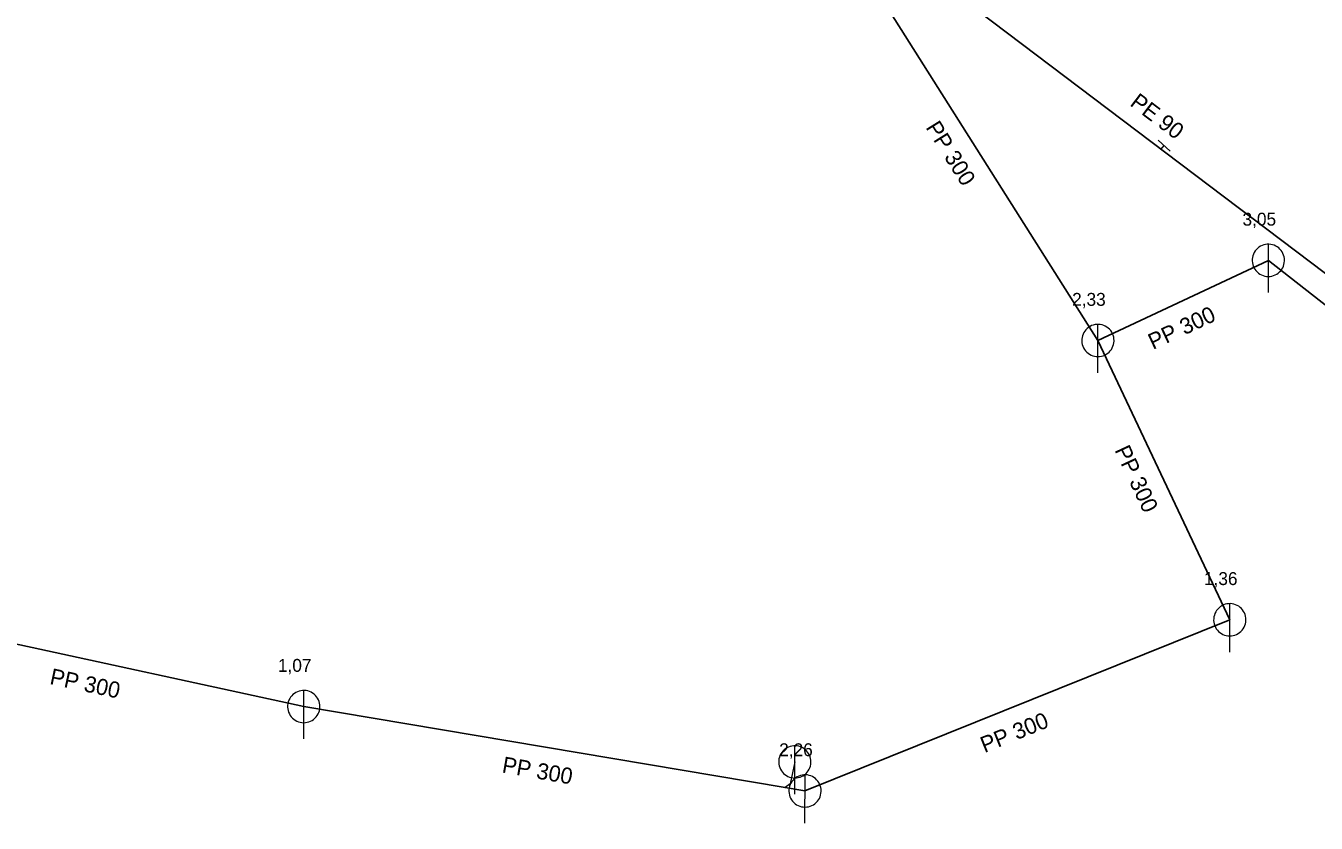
# Model space of a CAD drawing. Extents: x -683466 to -682479, y -996772 to -995963.
# Drawn here: x -683391.7 to -683311.7, y -996081.7 to -996032.3 of the extents above; entities that cross this region are included whole.
import ezdxf

# ---------------------------------------------------------------- set-up
doc = ezdxf.new("R2010")
doc.units = 0
doc.header["$LTSCALE"] = 0.4
doc.layers.add('1', color=7, linetype='Continuous')
for name, color, linetype, lineweight in [('11', 7, 'Continuous', 13), ('14', 7, 'Continuous', 25), ('17', 7, 'Continuous', 25), ('22', 7, 'Continuous', 13), ('34', 7, 'Continuous', 13)]:
    doc.layers.add(name, color=color, linetype=linetype, lineweight=lineweight)

msp = doc.modelspace()

# ---------------------------------------------------------------- linework, layer by layer
at = {"layer": '11'}
msp.add_lwpolyline([(-683344.05, -996077.91), (-683344.339, -996079.274), (-683344.657, -996079.502)], dxfattribs=at)
at = {"layer": '14'}
for p, q in [((-683340.109, -996028.32), (-683325.27, -996051.789)), ((-683374.48, -996074.48), (-683399.35, -996069.07)), ((-683317.1, -996069.1), (-683343.42, -996079.71))]:
    msp.add_line(p, q, dxfattribs=at)
at = {"layer": '14', "lineweight": 13}
msp.add_line((-683321.354, -996039.926), (-683321.16, -996039.71), dxfattribs=at)
at = {"layer": '14'}
for points in [[(-683314.71, -996046.82), (-683325.27, -996051.789), (-683317.1, -996069.1)], [(-683291.78, -996064.829), (-683303.509, -996055.596), (-683305.57, -996053.982), (-683314.71, -996046.82)], [(-683343.42, -996079.71), (-683344.657, -996079.502), (-683374.48, -996074.48)]]:
    msp.add_lwpolyline(points, dxfattribs=at)
at = {"layer": '17'}
msp.add_lwpolyline([(-683345.87, -996001.27), (-683340.96, -996022.3), (-683339.832, -996025.943), (-683304.056, -996053.017), (-683282.79, -996067.766), (-683274.905, -996069.189), (-683269.5, -996070.27), (-683248.91, -996070.167), (-683229.542, -996070.96), (-683219.888, -996069.96)], dxfattribs=at)
at = {"layer": '22'}
for p, q in [((-683314.71, -996048.82), (-683314.709, -996045.82)), ((-683325.27, -996053.789), (-683325.269, -996050.789)), ((-683317.1, -996071.1), (-683317.099, -996068.1)), ((-683374.48, -996076.48), (-683374.479, -996073.48)), ((-683344.05, -996079.91), (-683344.049, -996076.91)), ((-683343.42, -996081.71), (-683343.419, -996078.71))]:
    msp.add_line(p, q, dxfattribs=at)
for points in [[(-683313.71, -996046.82), (-683313.715, -996046.711), (-683313.733, -996046.603), (-683313.763, -996046.497), (-683313.803, -996046.396), (-683313.855, -996046.299), (-683313.917, -996046.209), (-683313.989, -996046.126), (-683314.069, -996046.052), (-683314.157, -996045.986), (-683314.251, -996045.931), (-683314.351, -996045.886), (-683314.456, -996045.853), (-683314.563, -996045.831), (-683314.672, -996045.821), (-683314.782, -996045.823), (-683314.89, -996045.837), (-683314.997, -996045.862), (-683315.1, -996045.899), (-683315.198, -996045.948), (-683315.29, -996046.006), (-683315.376, -996046.075), (-683315.453, -996046.152), (-683315.522, -996046.238), (-683315.581, -996046.33), (-683315.629, -996046.428), (-683315.666, -996046.531), (-683315.692, -996046.638), (-683315.706, -996046.746), (-683315.709, -996046.856), (-683315.699, -996046.965), (-683315.678, -996047.072), (-683315.644, -996047.176), (-683315.6, -996047.276), (-683315.545, -996047.371), (-683315.479, -996047.459), (-683315.405, -996047.539), (-683315.322, -996047.611), (-683315.232, -996047.673), (-683315.136, -996047.725), (-683315.034, -996047.766), (-683314.929, -996047.796), (-683314.821, -996047.814), (-683314.711, -996047.82), (-683314.602, -996047.814), (-683314.494, -996047.796), (-683314.389, -996047.767), (-683314.287, -996047.726), (-683314.19, -996047.674), (-683314.1, -996047.612), (-683314.017, -996047.541), (-683313.942, -996047.461), (-683313.877, -996047.373), (-683313.821, -996047.279), (-683313.777, -996047.179), (-683313.743, -996047.075), (-683313.721, -996046.967), (-683313.711, -996046.858)], [(-683324.27, -996051.789), (-683324.275, -996051.68), (-683324.293, -996051.572), (-683324.323, -996051.466), (-683324.363, -996051.365), (-683324.415, -996051.268), (-683324.477, -996051.178), (-683324.549, -996051.095), (-683324.629, -996051.021), (-683324.717, -996050.955), (-683324.811, -996050.9), (-683324.911, -996050.855), (-683325.016, -996050.822), (-683325.123, -996050.8), (-683325.232, -996050.79), (-683325.342, -996050.792), (-683325.45, -996050.806), (-683325.557, -996050.831), (-683325.66, -996050.868), (-683325.758, -996050.917), (-683325.85, -996050.975), (-683325.936, -996051.044), (-683326.013, -996051.121), (-683326.082, -996051.207), (-683326.141, -996051.299), (-683326.189, -996051.397), (-683326.226, -996051.5), (-683326.252, -996051.607), (-683326.266, -996051.715), (-683326.269, -996051.825), (-683326.259, -996051.934), (-683326.238, -996052.041), (-683326.204, -996052.145), (-683326.16, -996052.245), (-683326.105, -996052.34), (-683326.039, -996052.428), (-683325.965, -996052.508), (-683325.882, -996052.58), (-683325.792, -996052.642), (-683325.696, -996052.694), (-683325.594, -996052.735), (-683325.489, -996052.765), (-683325.381, -996052.783), (-683325.271, -996052.789), (-683325.162, -996052.783), (-683325.054, -996052.765), (-683324.949, -996052.736), (-683324.847, -996052.695), (-683324.75, -996052.643), (-683324.66, -996052.581), (-683324.577, -996052.51), (-683324.502, -996052.43), (-683324.437, -996052.342), (-683324.381, -996052.248), (-683324.337, -996052.148), (-683324.303, -996052.044), (-683324.281, -996051.936), (-683324.271, -996051.827)], [(-683316.1, -996069.1), (-683316.105, -996068.991), (-683316.123, -996068.883), (-683316.153, -996068.777), (-683316.193, -996068.676), (-683316.245, -996068.579), (-683316.307, -996068.489), (-683316.379, -996068.406), (-683316.459, -996068.332), (-683316.547, -996068.266), (-683316.641, -996068.211), (-683316.741, -996068.166), (-683316.846, -996068.133), (-683316.953, -996068.111), (-683317.062, -996068.101), (-683317.172, -996068.103), (-683317.28, -996068.117), (-683317.387, -996068.142), (-683317.49, -996068.179), (-683317.588, -996068.228), (-683317.68, -996068.286), (-683317.766, -996068.355), (-683317.843, -996068.432), (-683317.912, -996068.518), (-683317.971, -996068.61), (-683318.019, -996068.708), (-683318.056, -996068.811), (-683318.082, -996068.918), (-683318.096, -996069.026), (-683318.099, -996069.136), (-683318.089, -996069.245), (-683318.068, -996069.352), (-683318.034, -996069.456), (-683317.99, -996069.556), (-683317.935, -996069.651), (-683317.869, -996069.739), (-683317.795, -996069.819), (-683317.712, -996069.891), (-683317.622, -996069.953), (-683317.526, -996070.005), (-683317.424, -996070.046), (-683317.319, -996070.076), (-683317.211, -996070.094), (-683317.101, -996070.1), (-683316.992, -996070.094), (-683316.884, -996070.076), (-683316.779, -996070.047), (-683316.677, -996070.006), (-683316.58, -996069.954), (-683316.49, -996069.892), (-683316.407, -996069.821), (-683316.332, -996069.741), (-683316.267, -996069.653), (-683316.211, -996069.559), (-683316.167, -996069.459), (-683316.133, -996069.355), (-683316.111, -996069.247), (-683316.101, -996069.138)], [(-683373.48, -996074.48), (-683373.485, -996074.371), (-683373.503, -996074.263), (-683373.533, -996074.157), (-683373.573, -996074.056), (-683373.625, -996073.959), (-683373.687, -996073.869), (-683373.759, -996073.786), (-683373.839, -996073.712), (-683373.927, -996073.646), (-683374.021, -996073.591), (-683374.121, -996073.546), (-683374.226, -996073.513), (-683374.333, -996073.491), (-683374.442, -996073.481), (-683374.552, -996073.483), (-683374.66, -996073.497), (-683374.767, -996073.522), (-683374.87, -996073.559), (-683374.968, -996073.608), (-683375.06, -996073.666), (-683375.146, -996073.735), (-683375.223, -996073.812), (-683375.292, -996073.898), (-683375.351, -996073.99), (-683375.399, -996074.088), (-683375.436, -996074.191), (-683375.462, -996074.298), (-683375.476, -996074.406), (-683375.479, -996074.516), (-683375.469, -996074.625), (-683375.448, -996074.732), (-683375.414, -996074.836), (-683375.37, -996074.936), (-683375.315, -996075.031), (-683375.249, -996075.119), (-683375.175, -996075.199), (-683375.092, -996075.271), (-683375.002, -996075.333), (-683374.906, -996075.385), (-683374.804, -996075.426), (-683374.699, -996075.456), (-683374.591, -996075.474), (-683374.481, -996075.48), (-683374.372, -996075.474), (-683374.264, -996075.456), (-683374.159, -996075.427), (-683374.057, -996075.386), (-683373.96, -996075.334), (-683373.87, -996075.272), (-683373.787, -996075.201), (-683373.712, -996075.121), (-683373.647, -996075.033), (-683373.591, -996074.939), (-683373.547, -996074.839), (-683373.513, -996074.735), (-683373.491, -996074.627), (-683373.481, -996074.518)], [(-683343.05, -996077.91), (-683343.055, -996077.801), (-683343.073, -996077.693), (-683343.103, -996077.587), (-683343.143, -996077.486), (-683343.195, -996077.389), (-683343.257, -996077.299), (-683343.329, -996077.216), (-683343.409, -996077.142), (-683343.497, -996077.076), (-683343.591, -996077.021), (-683343.691, -996076.976), (-683343.796, -996076.943), (-683343.903, -996076.921), (-683344.012, -996076.911), (-683344.122, -996076.913), (-683344.23, -996076.927), (-683344.337, -996076.952), (-683344.44, -996076.989), (-683344.538, -996077.038), (-683344.63, -996077.096), (-683344.716, -996077.165), (-683344.793, -996077.242), (-683344.862, -996077.328), (-683344.921, -996077.42), (-683344.969, -996077.518), (-683345.006, -996077.621), (-683345.032, -996077.728), (-683345.046, -996077.836), (-683345.049, -996077.946), (-683345.039, -996078.055), (-683345.018, -996078.162), (-683344.984, -996078.266), (-683344.94, -996078.366), (-683344.885, -996078.461), (-683344.819, -996078.549), (-683344.745, -996078.629), (-683344.662, -996078.701), (-683344.572, -996078.763), (-683344.476, -996078.815), (-683344.374, -996078.856), (-683344.269, -996078.886), (-683344.161, -996078.904), (-683344.051, -996078.91), (-683343.942, -996078.904), (-683343.834, -996078.886), (-683343.729, -996078.857), (-683343.627, -996078.816), (-683343.53, -996078.764), (-683343.44, -996078.702), (-683343.357, -996078.631), (-683343.282, -996078.551), (-683343.217, -996078.463), (-683343.161, -996078.369), (-683343.117, -996078.269), (-683343.083, -996078.165), (-683343.061, -996078.057), (-683343.051, -996077.948)], [(-683342.42, -996079.71), (-683342.425, -996079.601), (-683342.443, -996079.493), (-683342.473, -996079.387), (-683342.513, -996079.286), (-683342.565, -996079.189), (-683342.627, -996079.099), (-683342.699, -996079.016), (-683342.779, -996078.942), (-683342.867, -996078.876), (-683342.961, -996078.821), (-683343.061, -996078.776), (-683343.166, -996078.743), (-683343.273, -996078.721), (-683343.382, -996078.711), (-683343.492, -996078.713), (-683343.6, -996078.727), (-683343.707, -996078.752), (-683343.81, -996078.789), (-683343.908, -996078.838), (-683344, -996078.896), (-683344.086, -996078.965), (-683344.163, -996079.042), (-683344.232, -996079.128), (-683344.291, -996079.22), (-683344.339, -996079.318), (-683344.376, -996079.421), (-683344.402, -996079.528), (-683344.416, -996079.636), (-683344.419, -996079.746), (-683344.409, -996079.855), (-683344.388, -996079.962), (-683344.354, -996080.066), (-683344.31, -996080.166), (-683344.255, -996080.261), (-683344.189, -996080.349), (-683344.115, -996080.429), (-683344.032, -996080.501), (-683343.942, -996080.563), (-683343.846, -996080.615), (-683343.744, -996080.656), (-683343.639, -996080.686), (-683343.531, -996080.704), (-683343.421, -996080.71), (-683343.312, -996080.704), (-683343.204, -996080.686), (-683343.099, -996080.657), (-683342.997, -996080.616), (-683342.9, -996080.564), (-683342.81, -996080.502), (-683342.727, -996080.431), (-683342.652, -996080.351), (-683342.587, -996080.263), (-683342.531, -996080.169), (-683342.487, -996080.069), (-683342.453, -996079.965), (-683342.431, -996079.857), (-683342.421, -996079.748)]]:
    msp.add_lwpolyline(points, close=True, dxfattribs=at)
at = {"layer": '34'}
msp.add_line((-683321.532, -996039.376), (-683320.788, -996040.044), dxfattribs=at)

# ---------------------------------------------------------------- texts
at = {"layer": '1'}
for s, rotation, p in [('PE 90 ', 323, (-683323.342, -996037.185)), ('PP 300', 302, (-683335.97, -996038.579)), ('PP 300', 25, (-683321.858, -996052.377)), ('PP 300', 295, (-683324.26, -996058.578)), ('PP 300', 348, (-683390.267, -996073.076)), ('PP 300', 22, (-683332.299, -996077.367)), ('PP 300', 350, (-683362.237, -996078.554))]:
    msp.add_text(s, height=1, rotation=rotation, dxfattribs=at).set_placement(p)
for s, p in [('3,05', (-683316.31, -996044.667)), ('2,33', (-683326.869, -996049.637)), ('1,36', (-683318.7, -996066.947)), ('1,07', (-683376.08, -996072.327)), ('2,26', (-683345.02, -996077.557))]:
    msp.add_text(s, height=0.8, dxfattribs=at).set_placement(p)

doc.saveas('drawing.dxf')
